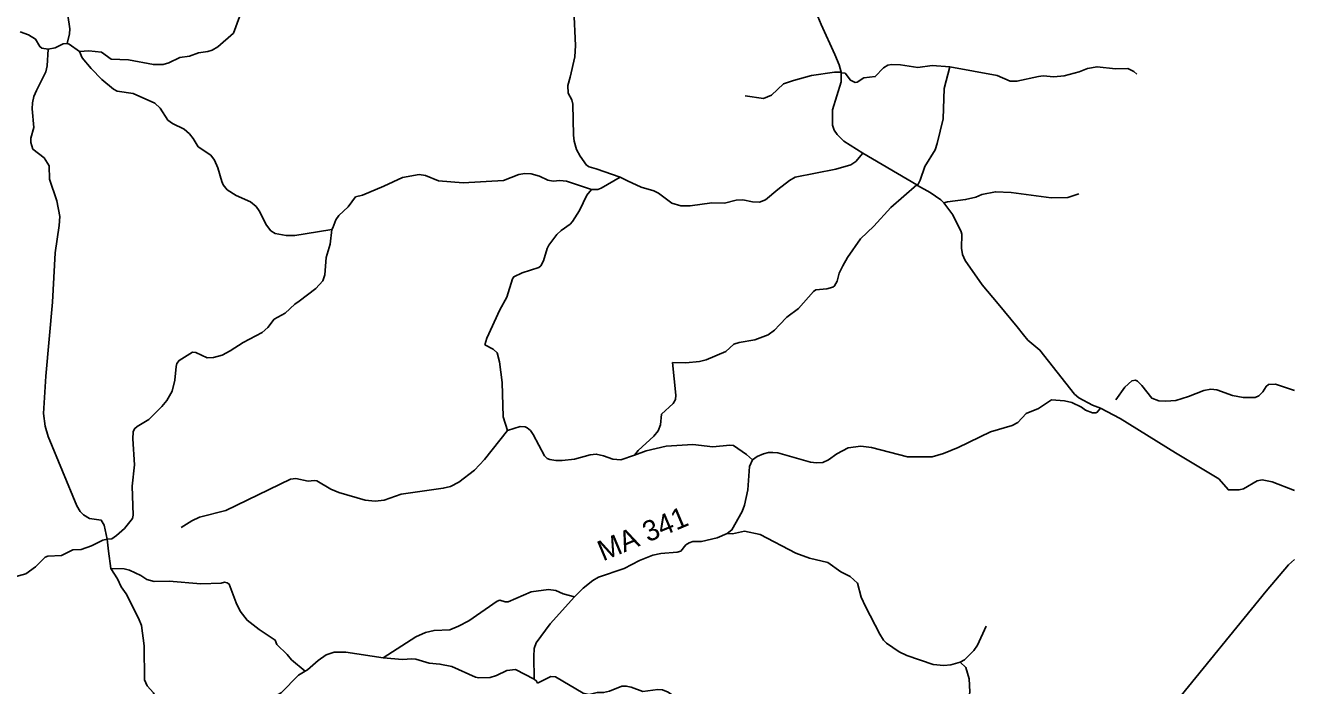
# Model space of a CAD drawing. Extents: x 332 to 501, y 9447 to 9559.
# Drawn here: x 476.49 to 500, y 9511.64 to 9523.87 of the extents above; entities that cross this region are included whole.
import ezdxf

# ---------------------------------------------------------------- set-up
doc = ezdxf.new("R2010")
doc.units = 0
for name, color, linetype in [('Level 2', 7, 'Continuous'), ('Level 31', 7, 'Continuous'), ('Level 4', 7, 'Continuous'), ('Level 5', 7, 'Continuous'), ('Level 6', 7, 'Continuous'), ('Level 7', 7, 'Continuous'), ('Level 8', 7, 'Continuous')]:
    doc.layers.add(name, color=color, linetype=linetype)

msp = doc.modelspace()

# ---------------------------------------------------------------- linework, layer by layer
at = {"layer": 'Level 2'}
msp.add_lwpolyline([(500, 9513.9763), (499.888, 9513.8804), (499.474, 9513.3939), (497.7622, 9511.2923)], dxfattribs=at)
at = {"layer": 'Level 4'}
for points in [[(491.5983, 9523.0065), (491.5642, 9523.1408), (491.4848, 9523.3377), (491.2298, 9523.8906), (491.0161, 9524.4183)], [(491.5284, 9521.8501), (491.4721, 9521.9354), (491.4431, 9522.0276), (491.4405, 9522.3103), (491.5984, 9522.8303), (491.5995, 9522.9942)], [(491.5995, 9522.9942), (491.5983, 9523.0065)], [(492.0041, 9521.5063), (491.6513, 9521.7309), (491.5284, 9521.8501)], [(492.0041, 9521.5063), (491.87, 9521.3501), (491.7788, 9521.2905), (491.5037, 9521.2122), (490.7515, 9521.0595), (490.643, 9521.0027), (490.4297, 9520.8332)], [(493.001, 9520.9183), (492.0041, 9521.5063)], [(487.6428, 9520.9956), (487.5055, 9521.0618)], [(488.1338, 9520.8085), (487.895, 9520.874), (487.6428, 9520.9956)], [(490.4297, 9520.8332), (490.2025, 9520.6408), (490.0885, 9520.5971), (489.9611, 9520.6071)], [(493.0174, 9520.9092), (493.001, 9520.9183)], [(493.5036, 9520.5859), (493.448, 9520.6442), (493.2517, 9520.7792), (493.0174, 9520.9092)], [(489.4426, 9520.5826), (489.2041, 9520.5875), (488.8053, 9520.5282), (488.6311, 9520.5294), (488.4632, 9520.5824), (488.2182, 9520.7631), (488.1338, 9520.8085)], [(489.9611, 9520.6071), (489.7809, 9520.6401), (489.6585, 9520.6379), (489.4426, 9520.5826)], [(493.826, 9520.0484), (493.672, 9520.3616), (493.5036, 9520.5859)], [(494.5073, 9518.7167), (494.2135, 9519.0666), (493.8992, 9519.5159), (493.8513, 9519.6295), (493.8273, 9519.7456), (493.8374, 9520.0082), (493.826, 9520.0484)], [(494.8588, 9518.287), (494.5073, 9518.7167)], [(494.9796, 9518.1432), (494.8588, 9518.287)], [(495.0567, 9518.0448), (494.9796, 9518.1432)], [(496.2544, 9516.8402), (496.0013, 9516.9714), (495.9231, 9517.0427), (495.2838, 9517.8587), (495.0567, 9518.0448)], [(489.9563, 9515.8229), (490.0459, 9515.8847), (490.1633, 9515.9365), (490.2525, 9515.9632), (490.3367, 9515.9632), (490.4271, 9515.9538), (491.0317, 9515.7851), (491.1453, 9515.7686), (491.2614, 9515.7775), (491.3687, 9515.828), (491.5214, 9515.9365), (491.7284, 9516.05), (491.9669, 9516.0779), (492.16, 9516.0564), (492.829, 9515.881), (493.2859, 9515.8835), (493.4963, 9515.9431), (493.7655, 9516.0539), (494.3688, 9516.3442), (494.7713, 9516.4591), (494.8761, 9516.5183), (495.0301, 9516.6811), (495.2548, 9516.7783), (495.4996, 9516.9374), (495.7369, 9516.9159), (495.8707, 9516.8869), (496.0505, 9516.801), (496.1269, 9516.748)], [(500, 9515.2575), (499.586, 9515.4156), (499.3971, 9515.4531), (499.3075, 9515.4392), (499.0521, 9515.2892), (498.9709, 9515.2705), (498.7742, 9515.2673), (498.5962, 9515.4758), (497.7917, 9515.9542), (496.7685, 9516.592)], [(489.4871, 9514.4604), (489.5777, 9514.5267), (489.7682, 9514.8662), (489.8124, 9514.9849), (489.8743, 9515.2727), (489.902, 9515.6993), (489.9563, 9515.8229)], [(488.6286, 9514.1354), (488.727, 9514.249)], [(488.727, 9514.249), (488.7851, 9514.2894), (488.8558, 9514.3096), (489.016, 9514.3153), (489.3038, 9514.3828), (489.4871, 9514.4604)], [(487.5841, 9513.8118), (487.8637, 9513.96), (488.1111, 9514.0609), (488.2612, 9514.0906), (488.5642, 9514.1127), (488.6286, 9514.1354)], [(486.6617, 9513.2888), (486.8199, 9513.4488), (487.0016, 9513.5914), (487.1064, 9513.652), (487.5841, 9513.8118)], [(485.9175, 9511.7639), (485.9087, 9512.183), (485.9175, 9512.3319), (485.9528, 9512.4379), (486.2115, 9512.7874), (486.6617, 9513.2888)]]:
    msp.add_lwpolyline(points, dxfattribs=at)
at = {"layer": 'Level 5'}
for points in [[(479.0431, 9523.1484), (479.1474, 9523.1773), (479.3544, 9523.2796), (479.5285, 9523.3036), (479.6977, 9523.3629), (479.8693, 9523.3919), (479.9513, 9523.4159), (480.0552, 9523.4744), (480.3471, 9523.7322), (480.4591, 9524.0345), (480.4981, 9524.0938), (480.8033, 9524.2982), (481.0684, 9524.3184), (481.3562, 9524.3866), (481.6995, 9524.3273), (481.8106, 9524.3222), (481.8686, 9524.3348), (481.9999, 9524.4105), (482.0768, 9524.4194), (482.2889, 9524.3399), (482.3419, 9524.3601), (482.3779, 9524.4485), (482.4014, 9524.4672)], [(476.3928, 9523.754), (476.5508, 9523.6961), (476.6788, 9523.6211), (476.76, 9523.4798), (476.7975, 9523.4501), (476.913, 9523.4329)], [(476.87, 9517.3757), (476.9929, 9518.7435), (477.0408, 9519.6623), (477.1153, 9520.1647), (477.1267, 9520.3363), (477.0724, 9520.6241), (476.9373, 9521.0254), (476.9323, 9521.2728), (476.8379, 9521.4204), (476.6317, 9521.5813), (476.5896, 9521.7015), (476.5927, 9521.785), (476.6458, 9521.9847), (476.6168, 9522.3254), (476.6231, 9522.439), (476.6496, 9522.5551), (476.6975, 9522.6687), (476.8705, 9523.012), (476.8944, 9523.1256), (476.913, 9523.4329)], [(476.913, 9523.4329), (477.0426, 9523.4595), (477.1936, 9523.5307), (477.2654, 9523.5355)], [(477.2654, 9523.5355), (477.3047, 9523.5257), (477.4913, 9523.3921)], [(477.4913, 9523.3921), (477.6694, 9523.4045), (477.9029, 9523.3768), (478.0808, 9523.2455), (478.4027, 9523.2342), (478.8621, 9523.1471), (479.0431, 9523.1484)], [(477.4913, 9523.3921), (477.5444, 9523.2703), (477.7072, 9523.0726), (477.9066, 9522.8719), (478.1263, 9522.694), (478.1906, 9522.6548), (478.4885, 9522.6107), (478.8899, 9522.4339), (478.9871, 9522.3393), (479.1297, 9522.1197), (479.213, 9522.0541), (479.4339, 9521.9518), (479.5285, 9521.866), (479.5973, 9521.7771)], [(493.6161, 9523.1068), (493.2884, 9523.1294), (493.0183, 9523.0966), (492.6977, 9523.142), (492.5361, 9523.1496), (492.4642, 9523.1357), (492.3859, 9523.0903), (492.2332, 9522.9249), (492.0187, 9522.8997), (491.896, 9522.8229), (491.8616, 9522.8166), (491.774, 9522.8573), (491.6738, 9522.9872), (491.5995, 9522.9942)], [(493.0174, 9520.9092), (493.0674, 9521.0085), (493.1533, 9521.2627), (493.3401, 9521.5707), (493.3818, 9521.6868), (493.4903, 9522.1412), (493.5105, 9522.7066), (493.6161, 9523.1068)], [(493.6161, 9523.1068), (494.4899, 9522.9464), (494.7335, 9522.8402), (494.8555, 9522.8402), (495.2569, 9522.9294)], [(495.2569, 9522.9294), (495.3435, 9522.9388), (495.539, 9522.9216), (495.7345, 9522.9372), (496.0067, 9523.0139), (496.1615, 9523.078), (496.3402, 9523.108), (496.6835, 9523.0688), (496.9132, 9523.0726), (497.0213, 9523.0221), (497.0777, 9522.9704)], [(486.5453, 9522.6204), (486.5375, 9522.7597), (486.5829, 9522.913)], [(487.0608, 9521.214), (486.9332, 9521.2513), (486.8847, 9521.2842), (486.7643, 9521.45), (486.6986, 9521.5752), (486.6532, 9521.727), (486.6423, 9521.8427), (486.6329, 9522.417), (486.611, 9522.4952), (486.5453, 9522.6204)], [(479.5973, 9521.7771), (479.6938, 9521.6262), (479.9239, 9521.4706), (479.995, 9521.3777), (480.0574, 9521.2325), (480.1268, 9520.9825), (480.1545, 9520.9219), (480.2302, 9520.826), (480.3969, 9520.7238), (480.6582, 9520.6064), (480.7642, 9520.5206), (480.821, 9520.441), (480.9561, 9520.1748), (481.0369, 9520.07), (481.1151, 9520.0182), (481.3234, 9519.9791), (481.4849, 9519.9804), (481.9025, 9520.0471)], [(486.9789, 9520.8306), (486.5107, 9520.9851), (486.3896, 9520.9989), (486.2684, 9520.9876), (486.1699, 9521.0078), (486.0147, 9521.081), (485.8595, 9521.1251), (485.7434, 9521.1276), (485.6298, 9521.11), (485.3445, 9520.9989), (484.5999, 9520.9548), (484.143, 9520.9926), (483.902, 9521.0926), (483.7878, 9521.1098), (483.4766, 9521.0557), (483.1333, 9520.8942), (482.7344, 9520.7301), (482.6086, 9520.6983)], [(487.5055, 9521.0618), (487.0608, 9521.214)], [(487.5055, 9521.0618), (487.1544, 9520.8575), (487.0913, 9520.8323), (486.9789, 9520.8306)], [(493.5036, 9520.5859), (493.5678, 9520.6065), (493.9067, 9520.6471), (494.0936, 9520.6922), (494.2072, 9520.7402), (494.4571, 9520.7919), (494.7474, 9520.7781), (495.4921, 9520.6783), (495.7975, 9520.6859), (496.0004, 9520.7552)], [(482.1695, 9520.0898), (482.1851, 9520.1241)], [(481.9025, 9520.0471), (482.1695, 9520.0898)], [(482.1695, 9520.0898), (482.1367, 9519.818)], [(482.1367, 9519.818), (482.0605, 9519.5715), (482.0403, 9519.2509), (482.0024, 9519.1423), (481.8724, 9518.9997), (481.5624, 9518.7667)], [(481.5624, 9518.7667), (481.4811, 9518.7107), (481.3031, 9518.5403), (481.0987, 9518.4305), (480.9813, 9518.279), (480.8778, 9518.1869), (480.5231, 9518.0001), (480.287, 9517.8423), (480.1369, 9517.7616), (479.9753, 9517.7186), (479.8566, 9517.7174), (479.6477, 9517.8144), (479.5868, 9517.8176), (479.3379, 9517.6681), (479.2975, 9517.6088), (479.2837, 9517.5521), (479.258, 9517.2999)], [(476.9105, 9516.2553), (476.8592, 9516.447), (476.825, 9516.6837), (476.87, 9517.3757)], [(479.258, 9517.2999), (479.2092, 9517.0952), (479.1095, 9516.9235), (479.0199, 9516.8111), (478.7775, 9516.5714), (478.5592, 9516.4426), (478.5138, 9516.401), (478.4885, 9516.3429), (478.4822, 9516.2117), (478.5118, 9515.7359), (478.4704, 9515.3347), (478.4891, 9514.8014), (478.4751, 9514.7405), (478.3283, 9514.5539), (478.1815, 9514.4227), (478.091, 9514.3618), (478.0067, 9514.3532)], [(487.7761, 9515.9124), (487.5204, 9515.8229), (487.369, 9515.8356), (487.1998, 9515.9012), (487.0661, 9515.9315), (486.9525, 9515.9201), (486.6647, 9515.8406), (486.435, 9515.8128), (486.3189, 9515.8103), (486.2053, 9515.8292), (486.1535, 9515.8532), (486.1081, 9515.8974), (485.8973, 9516.2925), (485.8468, 9516.3694), (485.7875, 9516.4174), (485.7509, 9516.4389), (485.6541, 9516.441), (485.4231, 9516.3707)], [(478.0067, 9514.3532), (477.9505, 9514.6171), (477.8974, 9514.7061), (477.6757, 9514.7374), (477.5648, 9514.8069), (477.5086, 9514.8678), (477.4462, 9514.9724), (476.9105, 9516.2553)], [(487.9881, 9515.9931), (487.7761, 9515.9124)], [(489.9563, 9515.8229), (489.8495, 9515.9253), (489.6059, 9516.0908), (489.5373, 9516.0968), (489.2268, 9516.0653), (488.8558, 9516.1082), (488.361, 9516.0766), (487.9881, 9515.9931)], [(481.7177, 9511.9323), (481.9165, 9512.1097), (482.0625, 9512.2109)], [(482.0625, 9512.2109), (482.2131, 9512.2624), (482.4296, 9512.2637), (483.1153, 9512.1571)], [(483.1153, 9512.1571), (483.4778, 9512.1236), (483.652, 9512.1412), (483.7214, 9512.1337), (483.9687, 9512.0573), (484.1707, 9512.0428), (484.3909, 9511.9948), (484.8296, 9511.8017), (484.8876, 9511.7891), (485.0971, 9511.7904), (485.2176, 9511.8289), (485.4102, 9511.9229), (485.5667, 9511.9431), (485.9175, 9511.7639)], [(479.8705, 9511.1532), (480.0434, 9511.1808), (480.3122, 9511.2704), (480.4296, 9511.3234), (480.6115, 9511.442), (480.6772, 9511.4635), (480.7226, 9511.466), (480.9068, 9511.4206), (481.0141, 9511.4269), (481.1744, 9511.4761), (481.2274, 9511.5108), (481.5505, 9511.8377), (481.6735, 9511.9073)], [(481.6735, 9511.9073), (481.7177, 9511.9323)], [(485.9175, 9511.7639), (485.9597, 9511.7272), (485.9784, 9511.6866)], [(485.9784, 9511.6866), (486.2235, 9511.8131)], [(486.2235, 9511.8131), (486.3125, 9511.8084), (486.8215, 9511.5023), (486.9324, 9511.4804), (487.0791, 9511.5132), (487.2009, 9511.5132), (487.3118, 9511.539), (487.5413, 9511.6311), (487.6209, 9511.6342), (487.7146, 9511.6131), (487.9285, 9511.535), (488.2033, 9511.5733), (488.2923, 9511.5624), (488.3985, 9511.5202), (488.678, 9511.3211), (488.7264, 9511.3102), (488.9517, 9511.3171), (489.0123, 9511.3032), (489.3303, 9511.1757), (489.5196, 9511.1429), (489.5556, 9511.1195)]]:
    msp.add_lwpolyline(points, dxfattribs=at)
at = {"layer": 'Level 6'}
for points in [[(477.7713, 9525.1348), (477.7321, 9524.9053), (477.5623, 9524.539), (477.4611, 9524.4001), (477.339, 9524.2761), (477.2904, 9524.1818), (477.2755, 9524.0657), (477.313, 9523.8115), (477.311, 9523.7181), (477.2654, 9523.5355)], [(487.1695, 9524.9235), (487.0943, 9524.8938), (487.0035, 9524.7997), (486.8907, 9524.4339), (486.676, 9524.2389), (486.6509, 9524.1684), (486.6776, 9523.5032), (486.6682, 9523.2894), (486.5829, 9522.913)], [(491.5983, 9523.0065), (491.4768, 9523.005), (491.0491, 9522.9448), (490.7153, 9522.8508), (490.5351, 9522.789), (490.3095, 9522.5837), (490.1607, 9522.5172), (489.8222, 9522.5681)], [(484.9988, 9517.958), (485.038, 9518.0807), (485.2791, 9518.603), (485.4111, 9518.8414), (485.5153, 9519.1791), (485.5381, 9519.2148), (485.6929, 9519.2903), (486.004, 9519.3909), (486.0402, 9519.421), (486.0884, 9519.5101), (486.1549, 9519.7425), (486.1867, 9519.8001), (486.3355, 9519.9987), (486.4169, 9520.0762), (486.5806, 9520.1884), (486.6273, 9520.241), (486.7573, 9520.4427), (486.8903, 9520.7317), (486.9789, 9520.8306)], [(482.1851, 9520.1241), (482.242, 9520.2747), (482.2996, 9520.3492), (482.4712, 9520.5131), (482.6086, 9520.6983)], [(485.2272, 9517.8074), (485.1585, 9517.8742), (484.9988, 9517.958)], [(485.4231, 9516.3707), (485.3431, 9516.6218), (485.3212, 9517.2594), (485.2736, 9517.6388), (485.2272, 9517.8074)], [(497.0514, 9517.3002), (496.9877, 9517.2877), (496.853, 9517.1734), (496.6869, 9516.9384)], [(500, 9517.1097), (499.6439, 9517.23), (499.5164, 9517.2235), (499.4726, 9517.1859), (499.4099, 9517.0824), (499.3347, 9517.0104), (499.272, 9516.9822), (499.0495, 9516.9822), (498.849, 9517.0198), (498.5575, 9517.1232), (498.451, 9517.1357), (498.3163, 9517.1092), (498.0343, 9516.9962), (497.7993, 9516.9273), (497.6144, 9516.9116), (497.4859, 9516.921), (497.3543, 9516.9649), (497.1725, 9517.1999), (497.0911, 9517.2814), (497.0514, 9517.3002)], [(485.4231, 9516.3707), (484.9941, 9515.8315)], [(484.9941, 9515.8315), (484.8109, 9515.6355), (484.5181, 9515.4102), (484.3653, 9515.3298), (484.2323, 9515.2981), (483.4532, 9515.1882), (483.1366, 9515.081), (482.9694, 9515.0586), (482.7825, 9515.0797), (482.2969, 9515.2227)], [(481.8917, 9515.4341), (481.8411, 9515.442), (481.7299, 9515.4272), (481.5019, 9515.4774), (481.4021, 9515.4673), (480.201, 9514.888), (479.7168, 9514.763), (479.5729, 9514.6945), (479.3754, 9514.5695)], [(482.2969, 9515.2227), (482.1497, 9515.2831), (481.8917, 9515.4341)], [(489.4871, 9514.4604), (489.5903, 9514.4572), (489.8086, 9514.5009), (490.0994, 9514.4415), (490.7619, 9514.0976), (491.0139, 9514.0064), (491.3534, 9513.9251), (491.5926, 9513.7535), (491.7683, 9513.6621), (491.9013, 9513.5391), (491.9698, 9513.284), (492.0502, 9513.1104), (492.3201, 9512.5944), (492.3866, 9512.4833), (492.4422, 9512.4278), (492.6734, 9512.2669), (492.8193, 9512.1984), (493.3056, 9512.0318), (493.5011, 9512.0169), (493.6321, 9512.0249), (493.8033, 9512.0748)], [(478.0067, 9514.3532), (477.9234, 9514.338), (477.713, 9514.2318), (477.5234, 9514.1653), (477.3706, 9514.1584), (477.1612, 9514.0543), (476.9071, 9514.0405), (476.8555, 9514.0216), (476.6798, 9513.845), (476.4992, 9513.715), (476.1627, 9513.6178), (475.8699, 9513.4193), (475.5821, 9513.2963), (475.4253, 9513.2626), (475.2973, 9513.1932), (475.1732, 9513.0811), (475.0561, 9512.8598), (475.0194, 9512.8231), (474.9646, 9512.7992)], [(478.0067, 9514.3532), (478.0283, 9514.1332)], [(478.0283, 9514.1332), (478.0732, 9513.8135)], [(481.6735, 9511.9073), (481.4193, 9512.1203), (481.3379, 9512.2217), (481.1493, 9512.4065), (481.1195, 9512.486), (480.8192, 9512.6847), (480.597, 9512.8536), (480.4679, 9513.0244), (480.3944, 9513.1733), (480.2663, 9513.5239), (480.2257, 9513.5477), (480.18, 9513.5577), (480.1175, 9513.5398), (479.7404, 9513.5269), (479.1569, 9513.5778), (478.8761, 9513.5699), (478.7401, 9513.6107), (478.627, 9513.6832), (478.4215, 9513.7826), (478.3223, 9513.8045), (478.0732, 9513.8135)], [(478.0732, 9513.8135), (478.1943, 9513.6239), (478.2648, 9513.4721), (478.359, 9513.341), (478.5872, 9512.8945), (478.6398, 9512.7586), (478.6924, 9512.3825), (478.6954, 9511.7493), (478.747, 9511.6411), (478.8661, 9511.5091), (478.9078, 9511.4168), (478.9589, 9511.0982)], [(486.6617, 9513.2888), (486.4524, 9513.3421), (486.3174, 9513.4017), (486.1814, 9513.4206), (485.8598, 9513.382), (485.435, 9513.1965), (485.3774, 9513.1926), (485.2802, 9513.2234), (485.2306, 9513.2046), (484.7075, 9512.8424), (484.514, 9512.7432), (484.3512, 9512.6787), (484.0613, 9512.6649), (483.9035, 9512.6282), (483.7243, 9512.549), (483.1153, 9512.1571)], [(493.8033, 9512.0748), (493.8871, 9512.1233), (494.0588, 9512.294), (494.1243, 9512.3933), (494.286, 9512.7465)]]:
    msp.add_lwpolyline(points, dxfattribs=at)
at = {"layer": 'Level 7'}
for points in [[(490.4591, 9518.3273), (490.595, 9518.468), (490.8094, 9518.6289), (491.0883, 9518.9468), (491.135, 9518.9776), (491.3354, 9518.9964), (491.4446, 9519.0242), (491.4793, 9519.048), (491.5259, 9519.1344), (491.5627, 9519.2843), (491.6301, 9519.4174), (491.7185, 9519.5724), (491.9567, 9519.9171), (492.2048, 9520.1544), (492.5214, 9520.503), (493.001, 9520.9183)], [(490.2476, 9518.1413), (490.3637, 9518.2287), (490.4591, 9518.3273)], [(488.4745, 9517.6297), (488.7251, 9517.6239), (488.9791, 9517.6497), (489.1032, 9517.6795), (489.4675, 9517.8314), (489.6134, 9517.9675), (489.7116, 9518.0002), (489.9995, 9518.0459), (490.2476, 9518.1413)], [(487.7761, 9515.9124), (487.8424, 9515.9982), (488.1302, 9516.2654), (488.2116, 9516.3607), (488.2573, 9516.4719), (488.2731, 9516.6686), (488.4905, 9516.8673), (488.5302, 9516.9408), (488.5362, 9517.0262), (488.4745, 9517.6297)], [(495.5181, 9508.5788), (495.2506, 9509.444), (495.1265, 9509.5741), (494.9846, 9509.8105), (494.9072, 9510.0519), (494.8874, 9510.2902), (494.8596, 9510.4064), (494.7554, 9510.6398), (494.6839, 9510.753), (494.5608, 9510.8771), (494.4238, 9510.9446), (494.27, 9510.9923), (494.1191, 9511.0181), (494.0556, 9511.0509), (493.997, 9511.1472), (493.9712, 9511.2445), (493.9672, 9511.4045), (493.9821, 9511.5276), (493.9702, 9511.766), (493.9116, 9511.9805), (493.8033, 9512.0748)]]:
    msp.add_lwpolyline(points, dxfattribs=at)
at = {"layer": 'Level 8'}
for points in [[(496.2544, 9516.8402), (496.4017, 9516.7823)], [(496.4017, 9516.7823), (496.3453, 9516.7076), (496.3157, 9516.6967), (496.2594, 9516.6967), (496.1269, 9516.748)], [(496.4017, 9516.7823), (496.7685, 9516.592)]]:
    msp.add_lwpolyline(points, dxfattribs=at)

# ---------------------------------------------------------------- texts
at = {"layer": 'Level 31'}
msp.add_text('MA 341', height=0.38, rotation=22.83365, dxfattribs=at).set_placement((487.1901, 9513.9427))

doc.saveas('drawing.dxf')
